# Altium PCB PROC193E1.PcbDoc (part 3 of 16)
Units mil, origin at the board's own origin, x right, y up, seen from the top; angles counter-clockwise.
Board outline 7700 x 2300 mil, 6 copper layers (Top Layer, GND 1, SIG 1, PWR, GND 2, Bottom Layer), stack 60.98 mil thick; 946 components, 667 nets, 9401 pads, 1730 vias.
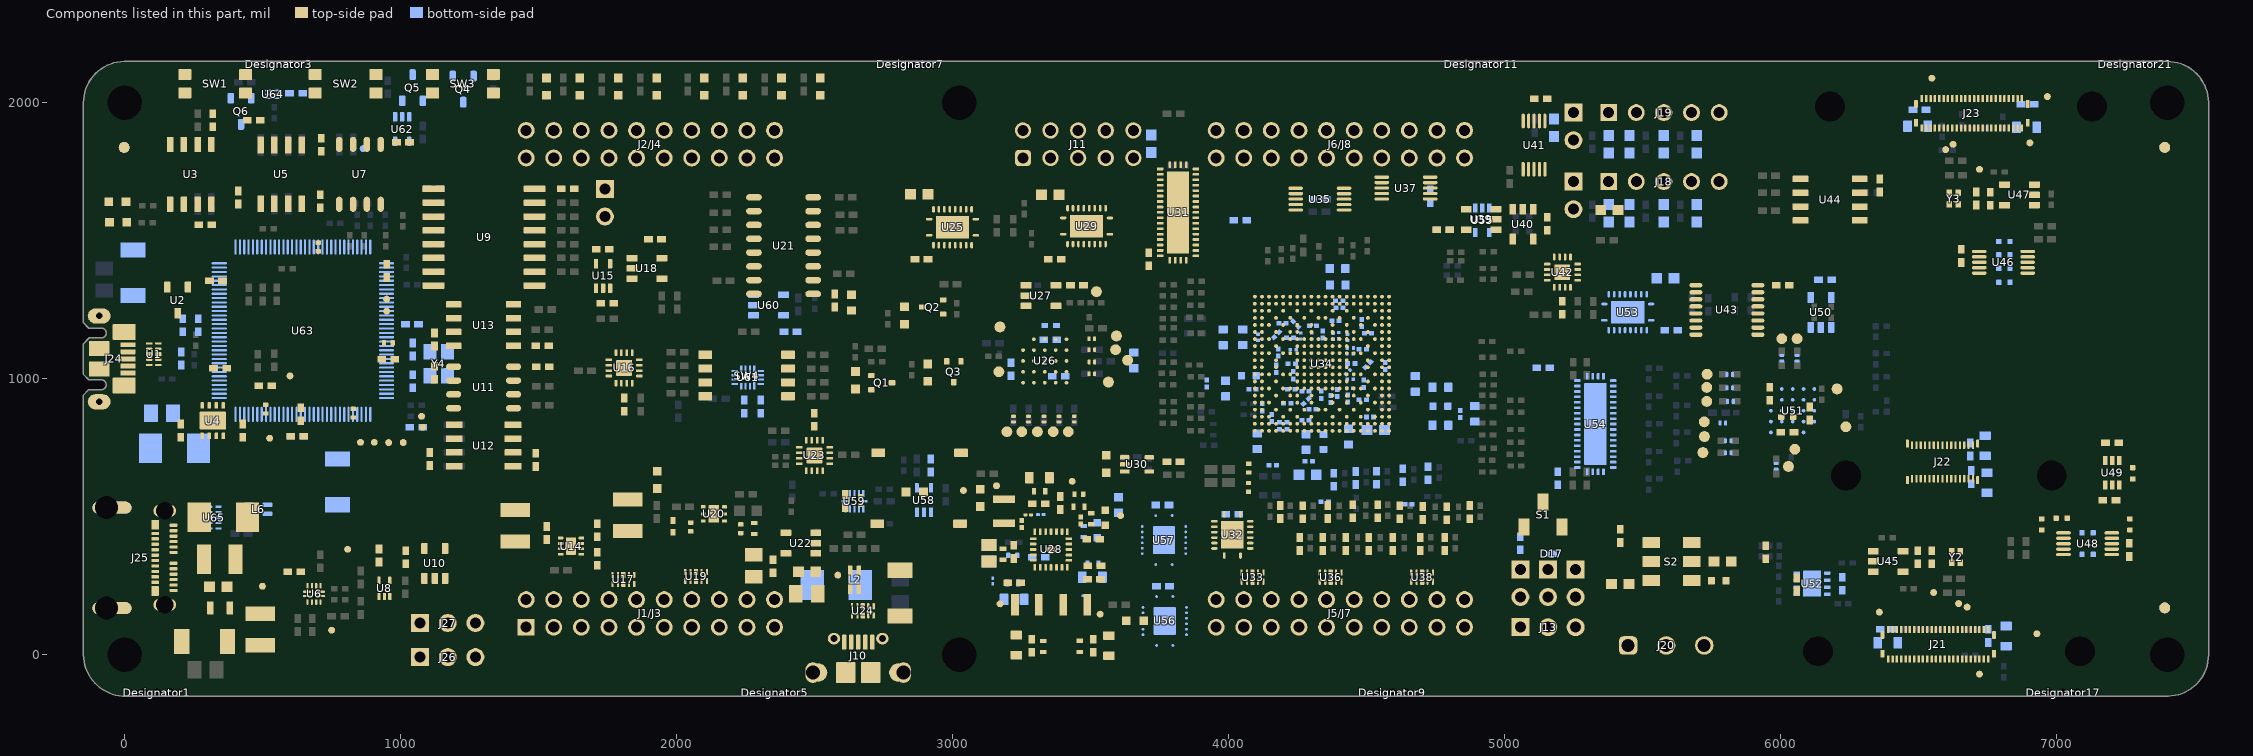
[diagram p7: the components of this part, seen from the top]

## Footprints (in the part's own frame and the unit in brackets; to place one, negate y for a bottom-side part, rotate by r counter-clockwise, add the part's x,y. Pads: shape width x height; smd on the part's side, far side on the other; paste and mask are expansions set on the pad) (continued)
BOOSTERPACK_40PIN_J5J7 [mm] "Receptacle, 2.54mm, 10x2, TH"
  round 1.55 hole 1.02: 41(1.27,11.43) 42(1.27,8.89) 43(1.27,6.35) 44(1.27,3.81) 45(1.27,1.27) 46(1.27,-1.27) 47(1.27,-3.81) 48(1.27,-6.35) 49(1.27,-8.89) 50(1.27,-11.43) 61(-1.27,11.43) 62(-1.27,8.89) 63(-1.27,6.35) 64(-1.27,3.81) 65(-1.27,1.27) 66(-1.27,-1.27) 67(-1.27,-3.81) 68(-1.27,-6.35) 69(-1.27,-8.89) 70(-1.27,-11.43)
  silkscreen extent -2.48,-12.95 2.48,12.95, body extent -2.48,-12.95 2.48,12.95, height 8.51
BoosterPack_40pin_J6J8 [mm] "Receptacle, 2.54mm, 10x2, TH"
  round 1.55 hole 1.02: 51(-1.27,-11.43) 52(-1.27,-8.89) 53(-1.27,-6.35) 54(-1.27,-3.81) 55(-1.27,-1.27) 56(-1.27,1.27) 57(-1.27,3.81) 58(-1.27,6.35) 59(-1.27,8.89) 60(-1.27,11.43) 71(1.27,-11.43) 72(1.27,-8.89) 73(1.27,-6.35) 74(1.27,-3.81) 75(1.27,-1.27) 76(1.27,1.27) 77(1.27,3.81) 78(1.27,6.35) 79(1.27,8.89) 80(1.27,11.43)
  silkscreen extent -7.62,-12.95 2.48,12.95, body extent -2.48,-12.95 2.48,12.95, height 8.51
BRAKE_WAY_HOLES1X3 [mil]
  round 27 hole 32 unplated mask+5.5: ""(-50,49.37) ""(0,49.37) ""(50,49.37)
CE_Mark_5mm [mil] "Minimum text height for CE Mark"
  silkscreen extent -138,-98 138,98
D0008A-MFG [mm]
  rrect17% 1.55x0.6 smd paste+0 mask+0: 1(-2.7,1.905) 2(-2.7,0.635) 3(-2.7,-0.635) 4(-2.7,-1.905) 5(2.7,-1.905) 6(2.7,-0.635) 7(2.7,0.635) 8(2.7,1.905)
  silkscreen extent -4.17,-2.5 1.5,2.5, body extent -3.57,-2.75 3.57,2.75, height 0.25
D0008B_HV [mm] "SOIC, 8-Leads, Body 4.9x3.9mm, Pitch 1.27mm, HV / Isolation option"
  rrect17% 1.4x0.6 smd: 1(-2.75,1.905) 2(-2.75,0.635) 3(-2.75,-0.635) 4(-2.75,-1.905) 5(2.75,-1.905) 6(2.75,-0.635) 7(2.75,0.635) 8(2.75,1.905)
  silkscreen extent -3.3,-2.5 0.9,2.5, body extent -3,-2.45 3,2.45, height 1.63
D0008B_N [mil] "SOIC, 8-Leads, Body 4.9x3.9mm, Pitch 1.27mm, IPC Medium Density"
  oval 55x23.62 smd: 1(-108.5,75) 2(-108.5,25) 3(-108.5,-25) 4(-108.5,-75) 5(108.5,-75) 6(108.5,-25) 7(108.5,25) 8(108.5,75)
  silkscreen extent -130,-98 35,98, body extent -118,-96 118,96, height 64
D0016A_N [mm] "SOIC, 16-Leads, Body 9.9x3.9mm, Pitch 1.27mm, IPC Medium Density"
  oval 1.45x0.6 smd: 1(-2.725,4.445) 2(-2.725,3.175) 3(-2.725,1.905) 4(-2.725,0.635) 5(-2.725,-0.635) 6(-2.725,-1.905) 7(-2.725,-3.175) 8(-2.725,-4.445) 9(2.725,-4.445) 10(2.725,-3.175) 11(2.725,-1.905) 12(2.725,-0.635) 13(2.725,0.635) 14(2.725,1.905) 15(2.725,3.175) 16(2.725,4.445)
  silkscreen extent -3.3,-5 0.9,5, body extent -3,-4.95 3,4.95, height 1.6
DBV0005A_N [mm] "SOT23, 5-Leads, Body 2.9x1.6mm, Pitch 0.95mm, Lead Span 2.8mm, IPC Medium Density"
  rrect17% 1x0.6 smd: 1(-1.375,0.95) 2(-1.375,0) 3(-1.375,-0.95) 4(1.375,-0.95) 5(1.375,0.95)
  silkscreen extent -0.25,-1.55 0.25,1.55, body extent -1.42,-1.46 1.42,1.46, height 1.09
DBZ0003A_N [mm] "SOT23, 3-Leads, Body 2.9x1.3mm, Pitch 0.95mm, Lead Span 2.4mm, IPC Medium Density"
  rrect17% 1x0.6 smd: 1(-1.2,0.95) 2(-1.2,-0.95) 3(1.2,0)
  silkscreen extent 0.2,-1.5 0.7,1.5, body extent -1.26,-1.46 1.26,1.46, height 0.98
DCK0005A_N [mm] "SOT353, 5-Leads, Body 2x1.3mm, Pitch 0.65mm, Lead Span 2.1mm, IPC Medium Density"
  rrect25% 0.85x0.4 smd: 1(-1.125,0.65) 2(-1.125,0) 3(-1.125,-0.65) 4(1.125,-0.65) 5(1.125,0.65)
  silkscreen extent -1.48,-1.02 0.55,1.1, body extent -1.14,-1 1.14,1, height 0.95
DCK0006A_N [mm] "SOT23, 6-Leads, Body 2x1.3mm, Pitch 0.65mm, Lead Span 2.1mm, IPC Medium Density"
  rrect25% 0.85x0.4 smd: 1(-1.125,0.65) 2(-1.125,0) 3(-1.125,-0.65) 4(1.125,-0.65) 5(1.125,0) 6(1.125,0.65)
  silkscreen extent -1.5,-1.09 0.51,1.09, body extent -1.14,-1 1.14,1, height 0.95
DGS0010A_N [mm] "TSSOP, 10-Leads, Body 3x3mm, Pitch 0.5mm, IPC Medium Density"
  oval 1.35x0.3 smd: 1(-2.225,1) 2(-2.225,0.5) 3(-2.225,0) 4(-2.225,-0.5) 5(-2.225,-1) 6(2.225,-1) 7(2.225,-0.5) 8(2.225,0) 9(2.225,0.5) 10(2.225,1)
  silkscreen extent -2.75,-1.55 0.9,1.55, body extent -2.45,-1.5 2.45,1.5, height 0.96
DPY0002A [mm] "X1SON-2"
  rrect57% 0.35x0.6 smd paste-0.5 mask-0.05: 1(-0.325,0) 2(0.325,0)
  rrect33% 0.3x0.5 on Bottom Paste: 1S(-0.35,0) 2S(0.35,0)
  silkscreen extent -0.85,-0.02 -0.8,0.02, body extent -0.5,-0.3 0.5,0.3, height 0.45
DQA0010A#1 [mm] "SON, 10-Leads, Body 1x2.5mm, Pitch 0.5mm, TI Recommended"
  rrect50% 0.565x0.2 smd: 1(-0.417,1) 2(-0.417,0.5) 4(-0.417,-0.5) 5(-0.417,-1) 6(0.417,-1) 7(0.417,-0.5) 9(0.417,0.5) 10(0.417,1)
  rrect28% 0.565x0.36 on Top Paste: 3(-0.417,0) 8(0.417,0)
  rrect25% 0.565x0.4 smd paste-0.2: 3(-0.417,0) 8(0.417,0)
  silkscreen extent -0.67,-1.45 0.55,1.45, body extent -0.55,-1.3 0.55,1.3, height 0.56
DQA0010A#2 [mm] "SON, 10-Leads, Body 1x2.5mm, Pitch 0.5mm, TI Recommended"
  rrect50% 0.565x0.2 smd: 1(-0.417,1) 2(-0.417,0.5) 4(-0.417,-0.5) 5(-0.417,-1) 6(0.417,-1) 7(0.417,-0.5) 9(0.417,0.5) 10(0.417,1)
  rrect28% 0.565x0.36 on Bottom Paste: 3(-0.417,0) 8(0.417,0)
  rrect25% 0.565x0.4 smd paste-0.2: 3(-0.417,0) 8(0.417,0)
  silkscreen extent -0.67,-1.45 0.55,1.45, body extent -0.55,-1.3 0.55,1.3, height 0.56
DRB0008B [mm] "SON, 8-Leads, Body 3x3mm, Pitch 0.65mm, Thermal Pad 2.4x1.65mm, TI Recommended"
  rrect33% 0.6x0.3 smd: 1(-1.4,0.975) 2(-1.4,0.325) 3(-1.4,-0.325) 4(-1.4,-0.975) 5(1.4,-0.975) 6(1.4,-0.325) 7(1.4,0.325) 8(1.4,0.975)
  rrect50% 1.47x1.06 on Top Paste: 9(0,0.63) 9(0,-0.63)
  rrect6% 1.65x2.4 smd paste-1.2: 9(0,0)
  silkscreen extent -1.73,-1.73 1.73,1.73, body extent -1.5,-1.5 1.5,1.5, height 0.96
DRB0008J [mm] "VSON-8"
  rrect33% 0.6x0.31 smd: 1(-1.4,0.975) 2(-1.4,0.325) 3(-1.4,-0.325) 4(-1.4,-0.975) 5(1.4,-0.975) 6(1.4,-0.325) 7(1.4,0.325) 8(1.4,0.975)
  rrect6% 1.65x2.4 smd paste-1.2: 9(0,0)
  silkscreen extent -1.73,-1.73 1.73,1.73, body extent -1.55,-1.55 1.55,1.55, height 1.01
DRL0005A [mm] "SOTFL, 5-Flat Leads, Body 1.2x1.6x0.6mm, Pitch 0.5mm, TI recommended"
  rrect33% 0.67x0.3 smd: 1(-0.74,0.5) 2(-0.74,0) 3(-0.74,-0.5) 4(0.74,-0.5) 5(0.74,0.5)
  silkscreen extent -0.9,-0.95 0.5,0.95, body extent -0.85,-0.85 0.85,0.85, height 0.62
DRV0006A [mm] "SON, 6-Leads, Body 2x2mm, Pitch 0.65mm, Thermal Pad 1.6x1mm, TI Recommended"
  rrect33% 0.45x0.3 smd: 1(-0.975,0.65) 2(-0.975,0) 3(-0.975,-0.65) 4(0.975,-0.65) 5(0.975,0) 6(0.975,0.65)
  rrect14% 1x0.7 on Top Paste: 7(0,0.45) 7(0,-0.45)
  rrect10% 1x1.6 smd paste-0.5: 7(0,0)
  silkscreen extent -1.05,-1.2 1.05,1.2, body extent -1.05,-1.05 1.05,1.05, height 0.81
DSF0006A [mm] "TI recommended land pattern"
  rrect59% 0.6x0.17 smd mask+0.045: 1(-0.4,0.35) 2(-0.4,0) 3(-0.4,-0.35) 4(0.4,-0.35) 5(0.4,0) 6(0.4,0.35)
  silkscreen extent -0.6,-0.63 0.6,0.63, body extent -0.5,-0.5 0.5,0.5, height 0.48
DSG0008B [mm] "SON, 8-Leads, Body 2x2mm, Pitch 0.5mm, Thermal Pad 1.6x0.9mm, TI Recommended"
  rrect14% 0.9x0.7 on Top Paste: 0(0,-0.45) 0(0,0.45)
  rrect40% 0.5x0.25 smd: 1(-0.95,0.75) 2(-0.95,0.25) 3(-0.95,-0.25) 4(-0.95,-0.75) 5(0.95,-0.75) 6(0.95,-0.25) 7(0.95,0.25) 8(0.95,0.75)
  rrect11% 0.9x1.6 smd paste-0.45: 9(0,0)
  silkscreen extent -1.07,-1.15 1.07,1.15, body extent -1,-1 1,1, height 0.77
DW0016A-MFG [mm]
  rrect17% 2x0.6 smd paste+0 mask+0: 1(-4.65,4.445) 2(-4.65,3.175) 3(-4.65,1.905) 4(-4.65,0.635) 5(-4.65,-0.635) 6(-4.65,-1.905) 7(-4.65,-3.175) 8(-4.65,-4.445) 9(4.65,-4.445) 10(4.65,-3.175) 11(4.65,-1.905) 12(4.65,-0.635) 13(4.65,0.635) 14(4.65,1.905) 15(4.65,3.175) 16(4.65,4.445)
  silkscreen extent -6.32,-5.25 3.15,5.25, body extent -5.75,-5.35 5.75,5.35, height 0.25
FCC_disclaimer [mil]
Fiducial10-20 [mm]
  round 1 smd mask+0.5: 1(0,0)
  Top Layer keep-out circle w1.178: c0,0 r0.5
FP-2012670005_CONN_USB_9MM39_8MM21-MFG [mm]
  rrect100% 1.1x2.1 hole 1.6 slot 0.6 at 0 deg paste-2539.97 mask+0: 1(-4.32,3.205) 2(4.32,3.205)
  rrect100% 1.1x3.6 smd paste-1000 mask+0: 3(-4.62,-1.655) 4(4.62,-1.655)
  rrect100% 1.1x3.6 smd far side paste-1000 mask+0: 3(-4.62,-1.655) 4(4.62,-1.655)
  rrect100% 0.6x2.1 hole 2.1 slot 0.6 at 0 deg paste-2539.97 mask+0: 3(-4.62,-2.155) 4(4.62,-2.155)
  rrect33% 0.3x0.7 smd paste+0 mask+0: A1(-3,4.015) A2(-2.5,4.015) A3(-2,4.015) A4(-1.5,4.015) A5(-1,4.015) A6(-0.5,4.015) A7(0.5,4.015) A8(1,4.015) A9(1.5,4.015) A10(2,4.015) A11(2.5,4.015) A12(3,4.015) B2(2.25,2.315) B3(1.75,2.315) B4(1.25,2.315) B5(0.75,2.315) B6(0.25,2.315) B7(-0.25,2.315) B8(-0.75,2.315) B9(-1.25,2.315) B10(-1.75,2.315) B11(-2.25,2.315)
  rrect14% 0.9x0.7 smd paste+0 mask+0: B1(3.05,2.315) B12(-3.05,2.315)
  silkscreen extent -4.77,0.52 4.77,5.04, body extent -5.27,-4.33 5.27,4.46, height 0.25
FP-416131160801_DIP_SW_1-MFG [mm]
  rrect13% 1.27x0.76 smd paste+0 mask+0: 1(-3.81,0) 2(3.81,0)
  silkscreen extent -5.12,-1.37 2.93,1.37, body extent -4.54,-1.47 4.54,1.47, height 0.25
FP-416131160804_SMT_SW-MFG [mm]
  rrect13% 0.76x1.27 smd paste+0 mask+0: 1(-1.905,-3.81) 2(-0.635,-3.81) 3(0.635,-3.81) 4(1.905,-3.81) 5(1.905,3.81) 6(0.635,3.81) 7(-0.635,3.81) 8(-1.905,3.81)
  silkscreen extent -3.27,-4.12 3.27,2.93, body extent -3.37,-4.54 3.37,4.54, height 0.25
FP-434351045816_SMT_SW_4MM7_4MM5-MFG [mm]
  rrect10% 1.2x1 smd paste+0 mask+0: 1(2.8,0.85) 2(2.8,-0.85) 3(-2.8,0.85) 4(-2.8,-0.85)
  silkscreen extent -2.4,0.73 4.07,1.85, body extent -3.5,-2.95 3.5,1.95, height 0.25
FP-629105150921_CONN_PTH_USB_8MM0_5MM6-MFG [mm]
  rrect25% 0.4x1.35 smd paste+0 mask+0: 1(-1.3,2.335) 2(-0.65,2.335) 3(0,2.335) 4(0.65,2.335) 5(1.3,2.335)
  rrect100% 1.15x1.05 hole 0.65 slot 0.75 at 0 deg paste-2539.97 mask+0: 6(-2.225,2.65) 7(2.225,2.65)
  rrect100% 1.35x1.9 hole 1.3 slot 0.75 at 0 deg paste-2539.97 mask+0: 8(-4.175,-0.47) 11(4.173,-0.47)
  round 1.71 smd paste+0 mask+0: 8(-3.699,-0.47) 11(3.699,-0.47)
  rrect6% 1.8x1.9 smd paste+0 mask+0: 9(-1.15,-0.47) 10(1.15,-0.47)
  Top Layer region: -2.6,-1.42 -4.35,-1.42 -4.541,-1.382 -4.704,-1.274 -4.812,-1.111 -4.85,-0.92 -4.85,-0.92 -4.85,-0.02 -4.812,0.171 -4.704,0.334 -4.541,0.442 -4.35,0.48 -4.35,0.48 -2.6,0.48
  Top Layer region: 2.6,0.48 4.35,0.48 4.541,0.442 4.704,0.334 4.812,0.171 4.85,-0.02 4.85,-0.02 4.85,-0.92 4.812,-1.111 4.704,-1.274 4.541,-1.382 4.35,-1.42 4.35,-1.42 2.6,-1.42
  silkscreen extent -3.8,0.86 3.8,3.71, body extent -4.95,-2.7 4.95,3.27, height 0.25
FP-ASCO-25.000MHZ-EK-T3_SMT4_1MM6_1MM2-MFG [mm]
  rrect20% 0.6x0.5 smd paste+0 mask+0: 1(-0.55,-0.4) 2(0.55,-0.4) 3(0.55,0.4) 4(-0.55,0.4)
  silkscreen extent -1.22,-1.35 1.22,0.65, body extent -0.8,-0.6 0.8,0.6, height 0.7
FP-BLM18EG121SN1D_0603-MFG [mm]
  rrect15% 0.65x0.7 smd paste+0 mask+0: 1(-0.675,0) 2(0.675,0)
  silkscreen extent -0.87,-0.8 0.87,0.8, body extent -1.1,-0.58 1.1,0.58, height 0.25
FP-BLM21PG300SN1D_0805-MFG [mm]
  rrect17% 0.6x1.2 smd paste-1000 mask-1000: 1(-0.9,0) 2(0.9,0)
  silkscreen extent -0.23,-0.72 0.23,0.72, body extent -1.3,-0.82 1.3,0.82, height 0.25
FP-CGA3E3X7S1A225K080AB_0603-MFG [mm]
  rrect14% 0.7x0.7 smd paste+0 mask+0: 1(-0.7,0) 2(0.7,0)
  silkscreen extent -0.95,-0.73 0.95,0.72, body extent -1.15,-0.65 1.15,0.65, height 0.25
FP-CGA4J3X7S1A106K125AE_0805-MFG [mm]
  rrect13% 0.8x1.05 smd paste+0 mask+0: 1(-0.925,0) 2(0.925,0)
  silkscreen extent -0.15,-0.75 0.15,0.75, body extent -1.2,-0.62 1.2,0.63, height 1.5
FP-CL10A335KP8NNNC_0603-MFG [mm]
  rrect13% 0.76x0.85 smd paste+0 mask+0: 1(-0.72,0) 2(0.72,0)
  silkscreen extent -0.85,-0.8 0.85,0.8, body extent -1.2,-0.55 1.2,0.55, height 0.25
"FP-CRCW020122R0FNED_0201 (0603 metric)-MFG" [mm]
  rrect36% 0.28x0.43 smd paste+0 mask+0: 1(-0.255,0) 2(0.255,0)
  body extent -0.3,-0.15 0.3,0.15, height 0.28
FP-DF40GB(1.5)-30DS-0.4V(58)_HDR30-MFG [mm]
  rrect50% 0.2x0.7 smd paste-1000 mask+0: 1(-2.8,-1.54) 2(-2.8,1.54) 3(-2.4,-1.54) 4(-2.4,1.54) 5(-2,-1.54) 6(-2,1.54) 7(-1.6,-1.54) 8(-1.6,1.54) 9(-1.2,-1.54) 10(-1.2,1.54) 11(-0.8,-1.54) 12(-0.8,1.54) 13(-0.4,-1.54) 14(-0.4,1.54) 15(0,-1.54) 16(0,1.54) 17(0.4,-1.54) 18(0.4,1.54) 19(0.8,-1.54) 20(0.8,1.54) 21(1.2,-1.54) 22(1.2,1.54) 23(1.6,-1.54) 24(1.6,1.54) 25(2,-1.54) 26(2,1.54) 27(2.4,-1.54) 28(2.4,1.54) 29(2.8,-1.54) 30(2.8,1.54)
  rrect36% 0.28x0.72 smd paste-1000 mask+0: 31(-3.24,1.68) 32(3.24,1.68) 33(-3.24,-1.68) 34(3.24,-1.68)
  silkscreen extent -4.47,-2.56 4.47,1.84, body extent -4.57,-2.14 4.57,2.14, height 0.25
FP-DF40GB-48DP-0.4V(58)_HDR48-MFG [mm]
  rrect43% 0.23x0.66 smd paste-1000 mask+0: 1(-4.6,-1.355) 2(-4.6,1.355) 3(-4.2,-1.355) 4(-4.2,1.355) 5(-3.8,-1.355) 6(-3.8,1.355) 7(-3.4,-1.355) 8(-3.4,1.355) 9(-3,-1.355) 10(-3,1.355) 11(-2.6,-1.355) 12(-2.6,1.355) 13(-2.2,-1.355) 14(-2.2,1.355) 15(-1.8,-1.355) 16(-1.8,1.355) 17(-1.4,-1.355) 18(-1.4,1.355) 19(-1,-1.355) 20(-1,1.355) 21(-0.6,-1.355) 22(-0.6,1.355) 23(-0.2,-1.355) 24(-0.2,1.355) 25(0.2,-1.355) 26(0.2,1.355) 27(0.6,-1.355) 28(0.6,1.355) 29(1,-1.355) 30(1,1.355) 31(1.4,-1.355) 32(1.4,1.355) 33(1.8,-1.355) 34(1.8,1.355) 35(2.2,-1.355) 36(2.2,1.355) 37(2.6,-1.355) 38(2.6,1.355) 39(3,-1.355) 40(3,1.355) 41(3.4,-1.355) 42(3.4,1.355) 43(3.8,-1.355) 44(3.8,1.355) 45(4.2,-1.355) 46(4.2,1.355) 47(4.6,-1.355) 48(4.6,1.355)
  rrect29% 0.35x0.7 smd paste-1000 mask+0: 49(-5.135,0.86) 50(5.135,0.86) 51(-5.135,-0.86) 52(5.135,-0.86)
  Top Layer keep-out region: -6.17,1.685 -4.86,1.685 -4.86,0.94 -5.46,0.94 -5.46,-0.94 -4.86,-0.94 -4.86,-1.685 -6.17,-1.685
  Top Layer keep-out region: 6.17,1.685 4.86,1.685 4.86,0.94 5.46,0.94 5.46,-0.94 4.86,-0.94 4.86,-1.685 6.17,-1.685
  silkscreen extent -5.53,-2.37 5.53,0.14, body extent -5.63,-1.79 5.63,1.79, height 0.25
FP-ERJ-2GEJ152X_0402-MFG [mm]
  rrect21% 0.475x0.5 smd paste+0 mask+0: 1(-0.512,0) 2(0.513,0)
  silkscreen extent -0.53,-0.63 0.53,0.63, body extent -0.5,-0.25 0.5,0.25, height 0.4
FP-GJM1555C1H120JB01D_0402-MFG [mm]
  rrect25% 0.4x0.5 smd paste+0 mask+0: 1(-0.4,0) 2(0.4,0)
  silkscreen extent -0.53,-0.63 0.53,0.63, body extent -0.7,-0.38 0.7,0.38, height 0.25
FP-GRM033C80J105ME05D_0201-MFG [mm]
  rrect33% 0.3x0.35 smd paste+0 mask+0: 1(-0.282,0) 2(0.283,0)
  body extent -0.3,-0.15 0.3,0.15, height 0.39
FP-GRM155C71A105KE11D_0402-MFG [mm]
  rrect25% 0.4x0.5 smd paste+0 mask+0: 1(-0.4,0) 2(0.4,0)
  silkscreen extent -0.55,-0.65 0.55,0.65, body extent -0.7,-0.4 0.7,0.4, height 0.25
FP-GRM155R71H104KE14D_0402-MFG [mm]
  rrect25% 0.4x0.5 smd paste+0 mask+0: 1(-0.4,0) 2(0.4,0)
  silkscreen extent -0.5,-0.65 0.5,0.65, body extent -0.7,-0.38 0.7,0.38, height 0.25
FP-IS25WX064-JHLE_TFBGA24-IPC_C [mm]
  round 0.34 smd paste+0 mask+0: A2(-1,2) A3(0,2) A4(1,2) A5(2,2) B1(-2,1) B2(-1,1) B3(0,1) B4(1,1) B5(2,1) C1(-2,0) C2(-1,0) C3(0,0) C4(1,0) C5(2,0) D1(-2,-1) D2(-1,-1) D3(0,-1) D4(1,-1) D5(2,-1) E1(-2,-2) E2(-1,-2) E3(0,-2) E4(1,-2) E5(2,-2)
  silkscreen extent -3.53,-4 3,4, body extent -3.1,-4.1 3.1,4.1, height 0.25
FP-KGM05CR51A106MH_0402-MFG [mm]
  rrect20% 0.6x0.5 smd paste+0 mask+0: 1(-0.55,0) 2(0.55,0)
  silkscreen extent -0.6,-0.63 0.6,0.63, body extent -0.5,-0.25 0.5,0.25, height 0.7
FP-MX25UW6445GXDQ00_BGA24-IPC_C [mm]
  round 0.34 smd paste+0 mask+0: A2(-1,2) A3(0,2) A4(1,2) A5(2,2) B1(-2,1) B2(-1,1) B3(0,1) B4(1,1) B5(2,1) C1(-2,0) C2(-1,0) C3(0,0) C4(1,0) C5(2,0) D1(-2,-1) D2(-1,-1) D3(0,-1) D4(1,-1) D5(2,-1) E1(-2,-2) E2(-1,-2) E3(0,-2) E4(1,-2) E5(2,-2)
  silkscreen extent -3.7,-4 3,4, body extent -3,-4 3,4, height 1.2
"FP-RC0201JR-070RL_0201 (0603 Metric)-IPC_C" [mil]
  rrect38% 13.94x10.34 smd paste+0 mask+0: 1(-10.01,0) 2(10.01,0)
  body extent -21,-10 21,10, height 10
IND_DLW21S [mm] "muRata"
  rrect25% 0.4x0.9 smd: 1(-0.4,0.85) 2(-0.4,-0.85) 3(0.4,-0.85) 4(0.4,0.85)
  silkscreen extent -1.23,0.66 -0.98,0.92, body extent -0.6,-1 0.6,1, height 1.21
Label_650x200 [mil] "Thermal Transfer Label"
  round 1 on Mech13: 0(0,0)
  silkscreen extent -325,-100 325,100, body extent -325,-100 325,100, height 1
MHNP_M2-5_PANHEAD_PHILLIPS [mil]
  round 103 hole 108 unplated mask+5.5: ""(0,0)
  Keep-Out Layer circle w1: c0,0 r108
MHNP_M3_PANHEAD_PHILLIPS#1 [mil]
  round 121 hole 126 unplated mask+5.5: ""(-4.17,0)
  Keep-Out Layer circle w1: c0,0 r126
MHNP_M3_PANHEAD_PHILLIPS#2 [mil]
  round 121 hole 126 unplated mask+5.5: ""(0,0)
  Keep-Out Layer circle w1: c0,0 r126
MISTRAL_LOGO_25 [mil]
  silkscreen extent 0,0 297,162
Molex_1051640001 [mm] "Receptacle, USB 2.0, Micro B, 5 Pos, 0.65mm Pitch, R/A, SMT"
  rrect22% 0.45x1.38 smd: 1(1.3,4.11) 2(0.65,4.11) 3(0,4.11) 4(-0.65,4.11) 5(-1.3,4.11)
  rrect7% 1.475x2.1 smd: 6(-2.462,3.75) 11(2.462,3.75)
  rrect100% 1.4x2.1 hole 0.6 slot 1.3 at 90 deg: 7(-3.95,1.45) 10(3.95,1.45)
  rrect7% 1.375x1.9 smd: 8(-0.937,1.45) 9(0.937,1.45)
  silkscreen extent 1.2,5.1 1.4,5.4, body extent -4.1,-0.7 4.1,4.47, height 2.45
NDK_NX3225GA [mm] "NDK"
  rect 1.2x1.4 smd: 1(-0.8,1.1) 2(-0.8,-1.1) 3(0.8,-1.1) 4(0.8,1.1)
  silkscreen extent -1.9,-0.1 1.4,2, body extent -1.3,-1.65 1.3,1.65, height 0.9
On-Shore_OSTTE030161 [mm] "Terminal Block, 3.5mm, 3x1, TH"
  rrect50% 1.7x1.7 hole 1.2: 1(-3.5,0)
  round 1.7 hole 1.2: 2(0,0) 3(3.5,0)
  silkscreen extent -5.25,-3.6 5.25,4.05, body extent -5.75,-3.6 5.75,3.4, height 8.4
PBC03SAAN [mm] "Sullins 100mil, 1x3, 230 mil above insulator"
  rect 1.65x1.65 hole 1.016: 1(-2.54,0)
  round 1.65 hole 1.016: 2(0,0) 3(2.54,0)
  silkscreen extent -3.81,-1.27 3.81,1.27, body extent -3.81,-1.27 3.81,1.27, height 8.38
PDT0128A [mm] "Thin QFP, 128-Leads, Body 14x14mm, Pitch 0.4mm"
  oval 1.4x0.2 smd: 1(-7.7,6.2) 2(-7.7,5.8) 3(-7.7,5.4) 4(-7.7,5) 5(-7.7,4.6) 6(-7.7,4.2) 7(-7.7,3.8) 8(-7.7,3.4) 9(-7.7,3) 10(-7.7,2.6) 11(-7.7,2.2) 12(-7.7,1.8) 13(-7.7,1.4) 14(-7.7,1) 15(-7.7,0.6) 16(-7.7,0.2) 17(-7.7,-0.2) 18(-7.7,-0.6) 19(-7.7,-1) 20(-7.7,-1.4) 21(-7.7,-1.8) 22(-7.7,-2.2) 23(-7.7,-2.6) 24(-7.7,-3) 25(-7.7,-3.4) 26(-7.7,-3.8) 27(-7.7,-4.2) 28(-7.7,-4.6) 29(-7.7,-5) 30(-7.7,-5.4) 31(-7.7,-5.8) 32(-7.7,-6.2) 65(7.7,-6.2) 66(7.7,-5.8) 67(7.7,-5.4) 68(7.7,-5) 69(7.7,-4.6) 70(7.7,-4.2) 71(7.7,-3.8) 72(7.7,-3.4) 73(7.7,-3) 74(7.7,-2.6) 75(7.7,-2.2) 76(7.7,-1.8) 77(7.7,-1.4) 78(7.7,-1) 79(7.7,-0.6) 80(7.7,-0.2) 81(7.7,0.2) 82(7.7,0.6) 83(7.7,1) 84(7.7,1.4) 85(7.7,1.8) 86(7.7,2.2) 87(7.7,2.6) 88(7.7,3) 89(7.7,3.4) 90(7.7,3.8) 91(7.7,4.2) 92(7.7,4.6) 93(7.7,5) 94(7.7,5.4) 95(7.7,5.8) 96(7.7,6.2)
  oval 0.2x1.4 smd: 33(-6.2,-7.7) 34(-5.8,-7.7) 35(-5.4,-7.7) 36(-5,-7.7) 37(-4.6,-7.7) 38(-4.2,-7.7) 39(-3.8,-7.7) 40(-3.4,-7.7) 41(-3,-7.7) 42(-2.6,-7.7) 43(-2.2,-7.7) 44(-1.8,-7.7) 45(-1.4,-7.7) 46(-1,-7.7) 47(-0.6,-7.7) 48(-0.2,-7.7) 49(0.2,-7.7) 50(0.6,-7.7) 51(1,-7.7) 52(1.4,-7.7) 53(1.8,-7.7) 54(2.2,-7.7) 55(2.6,-7.7) 56(3,-7.7) 57(3.4,-7.7) 58(3.8,-7.7) 59(4.2,-7.7) 60(4.6,-7.7) 61(5,-7.7) 62(5.4,-7.7) 63(5.8,-7.7) 64(6.2,-7.7) 97(6.2,7.7) 98(5.8,7.7) 99(5.4,7.7) 100(5,7.7) 101(4.6,7.7) 102(4.2,7.7) 103(3.8,7.7) 104(3.4,7.7) 105(3,7.7) 106(2.6,7.7) 107(2.2,7.7) 108(1.8,7.7) 109(1.4,7.7) 110(1,7.7) 111(0.6,7.7) 112(0.2,7.7) 113(-0.2,7.7) 114(-0.6,7.7) 115(-1,7.7) 116(-1.4,7.7) 117(-1.8,7.7) 118(-2.2,7.7) 119(-2.6,7.7) 120(-3,7.7) 121(-3.4,7.7) 122(-3.8,7.7) 123(-4.2,7.7) 124(-4.6,7.7) 125(-5,7.7) 126(-5.4,7.7) 127(-5.8,7.7) 128(-6.2,7.7)
  silkscreen extent -7.7,-6.3 6.3,6.99, body extent -8,-8 8,8, height 1.07
PW0016A_L [mm] "TSOP, 16-Leads, Body 5x4.4mm, Pitch 0.65mm, IPC High Density"
  oval 1.2x0.4 smd: 1(-2.85,2.275) 2(-2.85,1.625) 3(-2.85,0.975) 4(-2.85,0.325) 5(-2.85,-0.325) 6(-2.85,-0.975) 7(-2.85,-1.625) 8(-2.85,-2.275) 9(2.85,-2.275) 10(2.85,-1.625) 11(2.85,-0.975) 12(2.85,-0.325) 13(2.85,0.325) 14(2.85,0.975) 15(2.85,1.625) 16(2.85,2.275)
  silkscreen extent -2,-2.55 1.85,2.55, body extent -3.21,-2.5 3.21,2.5, height 1
RAY0024B-MFG [mm]
  rrect40% 0.625x0.25 smd paste+0 mask+0: 1(-1.637,1.5) 7(-1.637,-1.5) 13(1.637,-1.5) 19(1.637,1.5)
  rrect40% 0.6x0.25 smd paste+0 mask+0: 2(-1.65,1) 3(-1.65,0.5) 5(-1.65,-0.5) 6(-1.65,-1) 14(1.65,-1) 15(1.65,-0.5) 17(1.65,0.5) 18(1.65,1)
  rrect40% 0.6x0.25 smd paste+0 mask-1000: 4(-1.65,0) 16(1.65,0)
  rrect40% 0.25x0.6 smd paste+0 mask+0: 8(-1,-1.65) 9(-0.5,-1.65) 10(0,-1.65) 11(0.5,-1.65) 12(1,-1.65) 20(1,1.65) 21(0.5,1.65) 22(0,1.65) 23(-0.5,1.65) 24(-1,1.65)
  round 0.777 smd paste-1000 mask+0: ""(0.037,-0.003)
  Top Layer region: -1.95,0.075 -1.943,0.1 -1.925,0.118 -1.9,0.125 -1.9,0.125 -1.4,0.125 -1.378,0.12 -1.361,0.106 -1.361,0.106 -1.344,0.092 -1.322,0.088 -1.322,0.088 -0.426,0.088 -0.406,0.091 -0.39,0.102 -0.379,0.118 -0.375,0.138 -0.376,0.138 -0.376,0.601 -0.369,0.626 -0.35,0.644 -0.325,0.651 -0.326,0.651 0.456,0.651 0.48,0.644 0.499,0.626 0.505,0.601 0.505,0.601 0.505,0.1 0.509,0.081 0.52,0.065 0.536,0.054 0.556,0.05 0.556,0.05 1.303,0.05 1.324,0.055 1.342,0.068 1.352,0.088 1.352,0.088 1.362,0.107 1.379,0.12 1.4,0.125 1.4,0.125 1.9,0.125 1.925,0.118 1.943,0.1 1.95,0.075 1.95,0.075 1.95,-0.075 1.943,-0.1 1.925,-0.118 1.9,-0.125 1.9,-0.125 0.556,-0.125 0.536,-0.129 0.52,-0.14 0.509,-0.156 0.506,-0.175 0.505,-0.175 0.505,-0.601 0.499,-0.626 0.48,-0.644 0.456,-0.651 0.456,-0.651 -0.326,-0.651 -0.35,-0.644 -0.369,-0.626 -0.375,-0.601 -0.375,-0.601 -0.376,-0.138 -0.379,-0.118 -0.39,-0.102 -0.406,-0.091 -0.425,-0.088 -0.426,-0.087 -1.322,-0.088 -1.344,-0.092 -1.361,-0.106 -1.361,-0.106 -1.378,-0.12 -1.4,-0.125 -1.4,-0.125 -1.9,-0.125 -1.925,-0.118 -1.943,-0.1 -1.95,-0.075 -1.95,-0.075
  silkscreen extent -2.62,-2.17 2.17,2.17, body extent -1.75,-1.75 1.75,1.75, height 1
RGT0016A [mm] "QFN, 16-Leads, Body 3x3mm, Pitch 0.5mm, Thermal Pad 1.45x1.45mm, TI Recommended"
  rrect42% 0.6x0.24 smd: 1(-1.4,0.75) 2(-1.4,0.25) 3(-1.4,-0.25) 4(-1.4,-0.75) 9(1.4,-0.75) 10(1.4,-0.25) 11(1.4,0.25) 12(1.4,0.75)
  rrect42% 0.24x0.6 smd: 5(-0.75,-1.4) 6(-0.25,-1.4) 7(0.25,-1.4) 8(0.75,-1.4) 13(0.75,1.4) 14(0.25,1.4) 15(-0.25,1.4) 16(-0.75,1.4)
  rrect7% 1.34x1.34 on Top Paste: 17(0,0)
  rrect7% 1.45x1.45 smd paste-0.725: 17(0,0)
  silkscreen extent -1.72,-1.73 1.72,1.73, body extent -1.5,-1.5 1.5,1.5, height 1
RGY0016A [mm] "QFN, 16-Leads, Body 4x3.5mm, Pitch 0.5mm, Thermal Pad 2.55x2.05mm, TI Recommended"
  oval 0.24x0.6 smd: 1(-0.75,1.9) 8(-0.75,-1.9) 9(0.75,-1.9) 16(0.75,1.9)
  oval 0.6x0.24 smd: 2(-1.65,1.25) 3(-1.65,0.75) 4(-1.65,0.25) 5(-1.65,-0.25) 6(-1.65,-0.75) 7(-1.65,-1.25) 10(1.65,-1.25) 11(1.65,-0.75) 12(1.65,-0.25) 13(1.65,0.25) 14(1.65,0.75) 15(1.65,1.25)
  rect 2.05x2.55 smd paste-1.025: 17(0,0)
  silkscreen extent -1.97,-2.22 1.97,2.23, body extent -1.75,-2 1.75,2, height 1
RGY0016A-MFG [mm]
  round 0.252 smd paste-1000 mask+0: 1(-2.26,-0.75) 2(-1.25,-2) 3(-0.75,-2) 4(-0.25,-2) 5(0.25,-2) 6(0.75,-2) 7(1.25,-2) 8(2.25,-0.75) 9(2.25,0.75) 10(1.25,2) 11(0.75,2) 12(0.25,2) 13(-0.25,2) 14(-0.75,2) 15(-1.25,2) 16(-2.25,0.75)
  rrect5% 2.55x2.05 smd paste-1000 mask+0: 17(0,0)
  Top Layer region: -2.4,0.89 -1.69,0.89 -1.636,0.879 -1.591,0.849 -1.561,0.804 -1.55,0.75 -1.55,0.75 -1.561,0.696 -1.591,0.651 -1.636,0.621 -1.69,0.61 -1.69,0.61 -2.4,0.61
  Top Layer region: 2.4,-0.89 1.69,-0.89 1.636,-0.879 1.591,-0.849 1.561,-0.804 1.55,-0.75 1.55,-0.75 1.561,-0.696 1.591,-0.651 1.636,-0.621 1.69,-0.61 1.69,-0.61 2.4,-0.61
  Top Layer region: 2.4,0.61 1.69,0.61 1.636,0.621 1.591,0.651 1.561,0.696 1.55,0.75 1.55,0.75 1.561,0.804 1.591,0.849 1.636,0.879 1.69,0.89 1.69,0.89 2.4,0.89
  Top Layer region: -2.4,-0.61 -1.69,-0.61 -1.636,-0.621 -1.591,-0.651 -1.561,-0.696 -1.55,-0.75 -1.55,-0.75 -1.561,-0.804 -1.591,-0.849 -1.636,-0.879 -1.69,-0.89 -1.69,-0.89 -2.4,-0.89
  Top Layer region: -1.11,2.15 -1.11,1.44 -1.121,1.386 -1.151,1.341 -1.196,1.311 -1.25,1.3 -1.25,1.3 -1.304,1.311 -1.349,1.341 -1.379,1.386 -1.39,1.44 -1.39,1.44 -1.39,2.15
  Top Layer region: -0.61,2.15 -0.61,1.44 -0.621,1.386 -0.651,1.341 -0.696,1.311 -0.75,1.3 -0.75,1.3 -0.804,1.311 -0.849,1.341 -0.879,1.386 -0.89,1.44 -0.89,1.44 -0.89,2.15
  Top Layer region: -0.11,2.15 -0.11,1.44 -0.121,1.386 -0.151,1.341 -0.196,1.311 -0.25,1.3 -0.25,1.3 -0.304,1.311 -0.349,1.341 -0.379,1.386 -0.39,1.44 -0.39,1.44 -0.39,2.15
  Top Layer region: 0.39,2.15 0.39,1.44 0.379,1.386 0.349,1.341 0.304,1.311 0.25,1.3 0.25,1.3 0.196,1.311 0.151,1.341 0.121,1.386 0.11,1.44 0.11,1.44 0.11,2.15
  Top Layer region: 0.89,2.15 0.89,1.44 0.879,1.386 0.849,1.341 0.804,1.311 0.75,1.3 0.75,1.3 0.696,1.311 0.651,1.341 0.621,1.386 0.61,1.44 0.61,1.44 0.61,2.15
  Top Layer region: 1.39,2.15 1.39,1.44 1.379,1.386 1.349,1.341 1.304,1.311 1.25,1.3 1.25,1.3 1.196,1.311 1.151,1.341 1.121,1.386 1.11,1.44 1.11,1.44 1.11,2.15
  Top Layer region: 1.11,-2.15 1.11,-1.44 1.121,-1.386 1.151,-1.341 1.196,-1.311 1.25,-1.3 1.25,-1.3 1.304,-1.311 1.349,-1.341 1.379,-1.386 1.39,-1.44 1.39,-1.44 1.39,-2.15
  Top Layer region: 0.61,-2.15 0.61,-1.44 0.621,-1.386 0.651,-1.341 0.696,-1.311 0.75,-1.3 0.75,-1.3 0.804,-1.311 0.849,-1.341 0.879,-1.386 0.89,-1.44 0.89,-1.44 0.89,-2.15
  Top Layer region: 0.11,-2.15 0.11,-1.44 0.121,-1.386 0.151,-1.341 0.196,-1.311 0.25,-1.3 0.25,-1.3 0.304,-1.311 0.349,-1.341 0.379,-1.386 0.39,-1.44 0.39,-1.44 0.39,-2.15
  Top Layer region: -0.39,-2.15 -0.39,-1.44 -0.379,-1.386 -0.349,-1.341 -0.304,-1.311 -0.25,-1.3 -0.25,-1.3 -0.196,-1.311 -0.151,-1.341 -0.121,-1.386 -0.11,-1.44 -0.11,-1.44 -0.11,-2.15
  Top Layer region: -0.89,-2.15 -0.89,-1.44 -0.879,-1.386 -0.849,-1.341 -0.804,-1.311 -0.75,-1.3 -0.75,-1.3 -0.696,-1.311 -0.651,-1.341 -0.621,-1.386 -0.61,-1.44 -0.61,-1.44 -0.61,-2.15
  Top Layer region: -1.39,-2.15 -1.39,-1.44 -1.379,-1.386 -1.349,-1.341 -1.304,-1.311 -1.25,-1.3 -1.25,-1.3 -1.196,-1.311 -1.151,-1.341 -1.121,-1.386 -1.11,-1.44 -1.11,-1.44 -1.11,-2.15
  silkscreen extent -2.72,-1.83 2.07,1.83, body extent -2,-1.75 2,1.75, height 1
RGY0020A [mm] "QFN, 20-Leads, Body 4.5x3.5mm, Pitch 0.5mm, Thermal Pad 3.05x2.05mm, TI Recommended"
  oval 0.24x0.6 smd: 1(-0.75,2.15) 10(-0.75,-2.15) 11(0.75,-2.15) 20(0.75,2.15)
  oval 0.6x0.24 smd: 2(-1.65,1.75) 3(-1.65,1.25) 4(-1.65,0.75) 5(-1.65,0.25) 6(-1.65,-0.25) 7(-1.65,-0.75) 8(-1.65,-1.25) 9(-1.65,-1.75) 12(1.65,-1.75) 13(1.65,-1.25) 14(1.65,-0.75) 15(1.65,-0.25) 16(1.65,0.25) 17(1.65,0.75) 18(1.65,1.25) 19(1.65,1.75)
  rect 2.05x3.05 smd paste-1.025: 21(0,0)
  silkscreen extent -1.97,-2.47 1.97,2.48, body extent -1.75,-2.25 1.75,2.25, height 1
RSV0016A [mm] "QFN, 16-Leads, Body 1.8x2.6mm, Pitch 0.4mm, TI Recommended"
  rect 0.7x0.2 smd: 1(-0.75,0.6)
  rect 0.6x0.2 smd: 2(-0.8,0.2) 3(-0.8,-0.2) 4(-0.8,-0.6) 9(0.8,-0.6) 10(0.8,-0.2) 11(0.8,0.2) 12(0.8,0.6)
  rect 0.2x0.6 smd: 5(-0.6,-1.2) 6(-0.2,-1.2) 7(0.2,-1.2) 8(0.6,-1.2) 13(0.6,1.2) 14(0.2,1.2) 15(-0.2,1.2) 16(-0.6,1.2)
  silkscreen extent -1.08,-1.33 1.08,1.33, body extent -0.92,-1.32 0.92,1.33, height 0.56
RUA0042A-MFG [mm]
  rrect40% 0.6x0.25 smd paste+0 mask+0: 1(-1.65,4) 2(-1.65,3.5) 3(-1.65,3) 4(-1.65,2.5) 5(-1.65,2) 6(-1.65,1.5) 7(-1.65,1) 8(-1.65,0.5) 9(-1.65,0) 10(-1.65,-0.5) 11(-1.65,-1) 12(-1.65,-1.5) 13(-1.65,-2) 14(-1.65,-2.5) 15(-1.65,-3) 16(-1.65,-3.5) 17(-1.65,-4) 22(1.65,-4) 23(1.65,-3.5) 24(1.65,-3) 25(1.65,-2.5) 26(1.65,-2) 27(1.65,-1.5) 28(1.65,-1) 29(1.65,-0.5) 30(1.65,0) 31(1.65,0.5) 32(1.65,1) 33(1.65,1.5) 34(1.65,2) 35(1.65,2.5) 36(1.65,3) 37(1.65,3.5) 38(1.65,4)
  rrect40% 0.25x0.6 smd paste+0 mask+0: 18(-0.75,-4.4) 19(-0.25,-4.4) 20(0.25,-4.4) 21(0.75,-4.4) 39(0.75,4.4) 40(0.25,4.4) 41(-0.25,4.4) 42(-0.75,4.4)
  rrect5% 2.05x7.55 smd paste-1000 mask+0: 43(0,0)
  silkscreen extent -2.65,-4.55 1.8,4.55, body extent -1.75,-4.5 1.75,4.5, height 0.8
RUT0012A [mm] "QFN, 12-Leads, Body 1.7x2mm, Pitch 0.4mm, TI Recommended"
  rrect50% 0.7x0.2 smd: 1(-0.7,0.8) 2(-0.7,0.4) 3(-0.7,0) 4(-0.7,-0.4) 5(-0.7,-0.8) 7(0.7,-0.8) 8(0.7,-0.4) 9(0.7,0) 10(0.7,0.4) 11(0.7,0.8)
  rrect50% 0.2x0.7 smd: 6(0,-0.85) 12(0,0.85)
  silkscreen extent -0.9,-1.2 0.9,1.2, body extent -0.85,-1 0.85,1, height 0.55
RWB0012A [mm] "QFN, 12-Leads, Body 1.6x1.6mm, Pitch 0.4mm"
  rrect57% 0.7x0.2 smd paste-0.1: 1(-0.65,0.2) 2(-0.65,-0.2) 7(0.65,-0.2) 8(0.65,0.2)
  rrect57% 0.2x0.5 smd: 3(-0.6,-0.75) 4(-0.2,-0.75) 5(0.2,-0.75) 6(0.6,-0.75) 9(0.6,0.75) 10(0.2,0.75) 11(-0.2,0.75) 12(-0.6,0.75)
  silkscreen extent -0.92,-0.91 0.92,0.91, body extent -0.8,-0.8 0.8,0.8, height 0.4
Sitara_AM261_ZFG0304A [mm] "BGA, 304-Leads, Body 13.25x13.25mmx1.50mm, Pitch 0.65mm"
  round 0.35 smd mask+0.05: A1(-6.175,6.175) A2(-5.525,6.175) A3(-4.875,6.175) A4(-4.225,6.175) A5(-3.575,6.175) A6(-2.925,6.175) A7(-2.275,6.175) A8(-1.625,6.175) A9(-0.975,6.175) A10(-0.325,6.175) A11(0.325,6.175) A12(0.975,6.175) A13(1.625,6.175) A14(2.275,6.175) A15(2.925,6.175) A16(3.575,6.175) A17(4.225,6.175) A18(4.875,6.175) A19(5.525,6.175) A20(6.175,6.175) B1(-6.175,5.525) B2(-5.525,5.525) B3(-4.875,5.525) B4(-4.225,5.525) B5(-3.575,5.525) B6(-2.925,5.525) B7(-2.275,5.525) B8(-1.625,5.525) B9(-0.975,5.525) B10(-0.325,5.525) B11(0.325,5.525) B12(0.975,5.525) B13(1.625,5.525) B14(2.275,5.525) B15(2.925,5.525) B16(3.575,5.525) B17(4.225,5.525) B18(4.875,5.525) B19(5.525,5.525) B20(6.175,5.525) C1(-6.175,4.875) C2(-5.525,4.875) C3(-4.875,4.875) C5(-3.575,4.875) C7(-2.275,4.875) C9(-0.975,4.875) C12(0.975,4.875) C14(2.275,4.875) C16(3.575,4.875) C18(4.875,4.875) C19(5.525,4.875) C20(6.175,4.875) D1(-6.175,4.225) D2(-5.525,4.225) D4(-4.225,4.225) D6(-2.925,4.225) D8(-1.625,4.225) D10(-0.325,4.225) D11(0.325,4.225) D13(1.625,4.225) D15(2.925,4.225) D17(4.225,4.225) D19(5.525,4.225) D20(6.175,4.225) E1(-6.175,3.575) E2(-5.525,3.575) E3(-4.875,3.575) E5(-3.575,3.575) E7(-2.275,3.575) E9(-0.975,3.575) E12(0.975,3.575) E14(2.275,3.575) E16(3.575,3.575) E18(4.875,3.575) E19(5.525,3.575) E20(6.175,3.575) F1(-6.175,2.925) F2(-5.525,2.925) F4(-4.225,2.925) F6(-2.925,2.925) F7(-2.275,2.925) F9(-0.975,2.925) F12(0.975,2.925) F14(2.275,2.925) F15(2.925,2.925) F17(4.225,2.925) F19(5.525,2.925) F20(6.175,2.925) G1(-6.175,2.275) G2(-5.525,2.275) G3(-4.875,2.275) G5(-3.575,2.275) G6(-2.925,2.275) G7(-2.275,2.275) G8(-1.625,2.275) G9(-0.975,2.275) G10(-0.325,2.275) G11(0.325,2.275) G12(0.975,2.275) G13(1.625,2.275) G14(2.275,2.275) G15(2.925,2.275) G16(3.575,2.275) G18(4.875,2.275) G19(5.525,2.275) G20(6.175,2.275) H1(-6.175,1.625) H2(-5.525,1.625) H4(-4.225,1.625) H7(-2.275,1.625) H8(-1.625,1.625) H9(-0.975,1.625) H10(-0.325,1.625) H11(0.325,1.625) H12(0.975,1.625) H13(1.625,1.625) H14(2.275,1.625) H17(4.225,1.625) H19(5.525,1.625) H20(6.175,1.625) J1(-6.175,0.975) J2(-5.525,0.975) J3(-4.875,0.975) J5(-3.575,0.975) J6(-2.925,0.975) J7(-2.275,0.975) J8(-1.625,0.975) J9(-0.975,0.975) J10(-0.325,0.975) J11(0.325,0.975) J12(0.975,0.975) J13(1.625,0.975) J14(2.275,0.975) J15(2.925,0.975) J16(3.575,0.975) J18(4.875,0.975) J19(5.525,0.975) J20(6.175,0.975) K1(-6.175,0.325) K2(-5.525,0.325) K4(-4.225,0.325) K7(-2.275,0.325) K8(-1.625,0.325) K9(-0.975,0.325) K10(-0.325,0.325) K11(0.325,0.325) K12(0.975,0.325) K13(1.625,0.325) K14(2.275,0.325) K17(4.225,0.325) K19(5.525,0.325) K20(6.175,0.325) L1(-6.175,-0.325) L2(-5.525,-0.325) L4(-4.225,-0.325) L7(-2.275,-0.325) L8(-1.625,-0.325) L9(-0.975,-0.325) L10(-0.325,-0.325) L11(0.325,-0.325) L12(0.975,-0.325) L13(1.625,-0.325) L14(2.275,-0.325) L17(4.225,-0.325) L19(5.525,-0.325) L20(6.175,-0.325) M1(-6.175,-0.975) M2(-5.525,-0.975) M3(-4.875,-0.975) M5(-3.575,-0.975) M6(-2.925,-0.975) M7(-2.275,-0.975) M8(-1.625,-0.975) M9(-0.975,-0.975) M10(-0.325,-0.975) M11(0.325,-0.975) M12(0.975,-0.975) M13(1.625,-0.975) M14(2.275,-0.975) M15(2.925,-0.975) M16(3.575,-0.975) M18(4.875,-0.975) M19(5.525,-0.975) M20(6.175,-0.975) N1(-6.175,-1.625) N2(-5.525,-1.625) N4(-4.225,-1.625) N7(-2.275,-1.625) N8(-1.625,-1.625) N9(-0.975,-1.625) N10(-0.325,-1.625) N11(0.325,-1.625) N12(0.975,-1.625) N13(1.625,-1.625) N14(2.275,-1.625) N17(4.225,-1.625) N19(5.525,-1.625) N20(6.175,-1.625) P1(-6.175,-2.275) P2(-5.525,-2.275) P3(-4.875,-2.275) P5(-3.575,-2.275) P6(-2.925,-2.275) P7(-2.275,-2.275) P8(-1.625,-2.275) P9(-0.975,-2.275) P10(-0.325,-2.275) P11(0.325,-2.275) P12(0.975,-2.275) P13(1.625,-2.275) P14(2.275,-2.275) P15(2.925,-2.275) P16(3.575,-2.275) P18(4.875,-2.275) P19(5.525,-2.275) P20(6.175,-2.275) R1(-6.175,-2.925) R2(-5.525,-2.925) R4(-4.225,-2.925) R6(-2.925,-2.925) R7(-2.275,-2.925) R9(-0.975,-2.925) R12(0.975,-2.925) R14(2.275,-2.925) R15(2.925,-2.925) R17(4.225,-2.925) R19(5.525,-2.925) R20(6.175,-2.925) T1(-6.175,-3.575) T2(-5.525,-3.575) T3(-4.875,-3.575) T5(-3.575,-3.575) T7(-2.275,-3.575) T9(-0.975,-3.575) T12(0.975,-3.575) T14(2.275,-3.575) T16(3.575,-3.575) T18(4.875,-3.575) T19(5.525,-3.575) T20(6.175,-3.575) U1(-6.175,-4.225) U2(-5.525,-4.225) U4(-4.225,-4.225) U6(-2.925,-4.225) U8(-1.625,-4.225) U10(-0.325,-4.225) U11(0.325,-4.225) U13(1.625,-4.225) U15(2.925,-4.225) U17(4.225,-4.225) U19(5.525,-4.225) U20(6.175,-4.225) V1(-6.175,-4.875) V2(-5.525,-4.875) V3(-4.875,-4.875) V5(-3.575,-4.875) V7(-2.275,-4.875) V9(-0.975,-4.875) V12(0.975,-4.875) V14(2.275,-4.875) V16(3.575,-4.875) V18(4.875,-4.875) V19(5.525,-4.875) V20(6.175,-4.875) W1(-6.175,-5.525) W2(-5.525,-5.525) W3(-4.875,-5.525) W4(-4.225,-5.525) W5(-3.575,-5.525) W6(-2.925,-5.525) W7(-2.275,-5.525) W8(-1.625,-5.525) W9(-0.975,-5.525) W10(-0.325,-5.525) W11(0.325,-5.525) W12(0.975,-5.525) W13(1.625,-5.525) W14(2.275,-5.525) W15(2.925,-5.525) W16(3.575,-5.525) W17(4.225,-5.525) W18(4.875,-5.525) W19(5.525,-5.525) W20(6.175,-5.525) Y1(-6.175,-6.175) Y2(-5.525,-6.175) Y3(-4.875,-6.175) Y4(-4.225,-6.175) Y5(-3.575,-6.175) Y6(-2.925,-6.175) Y7(-2.275,-6.175) Y8(-1.625,-6.175) Y9(-0.975,-6.175) Y10(-0.325,-6.175) Y11(0.325,-6.175) Y12(0.975,-6.175) Y13(1.625,-6.175) Y14(2.275,-6.175) Y15(2.925,-6.175) Y16(3.575,-6.175) Y17(4.225,-6.175) Y18(4.875,-6.175) Y19(5.525,-6.175) Y20(6.175,-6.175)
  silkscreen extent -6.96,6.71 -6.71,6.96, body extent -6.63,-6.63 6.63,6.63, height 1.5
SMB-Bi [mil] "Molded Diode, 2-Leads, Body 5.4x3.6mm, IPC Medium Density, based on OnSemi component dimensions"
  rect 85x107.99 smd: 1(-87.01,0) 2(87.01,0)
  silkscreen extent -125,-79 125,79, body extent -104,-73 104,73, height 89
SOIC-8 [mm] "duplicate of SO-8.  SOIC, 8-Leads, Body 5.0x4.0mm (max), Pitch 1.27mm, IPC Medium Density"
  rrect17% 1.45x0.6 smd: 1(-2.725,1.905) 2(-2.725,0.635) 3(-2.725,-0.635) 4(-2.725,-1.905) 5(2.725,-1.905) 6(2.725,-0.635) 7(2.725,0.635) 8(2.725,1.905)
  silkscreen extent -3.5,-2.5 0.9,2.5, body extent -3,-2.45 3,2.45, height 1.63
SOT-23 [mm] "SOT23, 3-Leads, Body 2.9x1.3mm, Pitch 0.95mm, Lead Span 2.5mm, IPC Medium Density"
  rrect50% 1x0.6 smd: 1(-1.2,0.95) 2(-1.2,-0.95) 3(1.2,0)
  silkscreen extent -1.63,-1.5 0.7,1.5, body extent -1.16,-1.45 1.21,1.45, height 1
SOT-323 [mm] "Diodes Inc recommended land pattern.  2016-02-24"
  rrect21% 0.6x0.47 smd: 1(-0.95,0.65) 2(-0.95,-0.65) 3(0.95,0)
  silkscreen extent -1.14,-1.22 0.77,1.22, body extent -1.13,-1.13 1.12,1.12, height 1.13
Sullins_PBC02SAAN [mm] "Sullins 100mil, 1x2, 230 mil above insulator"
  rect 1.65x1.65 hole 1.016: 1(0,1.27)
  round 1.65 hole 1.016: 2(0,-1.27)
  silkscreen extent -1.27,-2.54 1.94,2.54, body extent -1.27,-2.54 1.27,2.54, height 8.38
Sullins_PxC05SAAN [mm] "Header, 2.54mm, 5x1, TH"
  rect 1.55x1.55 hole 1.016: 1(-5.08,0)
  round 1.55 hole 1.016: 2(-2.54,0) 3(0,0) 4(2.54,0) 5(5.08,0)
  silkscreen extent -6.35,-1.75 6.35,1.27, body extent -6.35,-1.27 6.35,1.27, height 5.84
Sullins_xxPC005DAAN-RC [mm] "Header, 2.54mm, 5x2, TH"
  rrect50% 1.5x1.5 hole 1: 1(-1.27,5.08)
  round 1.5 hole 1: 2(1.27,5.08) 3(-1.27,2.54) 4(1.27,2.54) 5(-1.27,0) 6(1.27,0) 7(-1.27,-2.54) 8(1.27,-2.54) 9(-1.27,-5.08) 10(1.27,-5.08)
  body extent -2.5,-6.35 2.5,6.35, height 8.34
SW_CAS-120TA [mm] "COPAL ELECTRONICS"
  rect 1.6x1 smd: 1(-1.15,1.75) 2(1.15,0) 3(-1.15,-1.75)
  silkscreen extent -2,-2.85 1.4,2.93, body extent -1.4,-2.85 1.4,2.85, height 2.51
SW_CAS-D20TA [mm] "SMD, 6-Leads, Body 5.4x3.9mm, Pitch 1.75mm"
  rect 1.6x1 smd: 1(-1.85,1.75) 2(-1.85,0) 3(-1.85,-1.75) 4(1.85,1.75) 5(1.85,0) 6(1.85,-1.75)
  silkscreen extent -1.95,-2.7 1.95,2.9, body extent -2.1,-2.7 2.1,2.7, height 2.5
TFM252012 [mm] "SMD, 2-Leads, Body 2.5x2mm"
  rect 0.7x2 smd: 1(-1.1,0) 2(1.1,0)
  silkscreen extent -0.45,-1.1 0.45,1.1, body extent -1.35,-1.1 1.35,1.1, height 1.2
TI_Stacked_Overlay_Small [mil]
  silkscreen extent -418,-98 418,98
TP_25MIL-SMT [mil]
  round 25 smd mask-2.5: 1(0,0)
TP_SM_1MM [mm] "1mm Test Point, SMT"
  round 1 smd paste-0.5: 1(0,0)
WEEE_Minimum [mil] "WEEElie bin"
  silkscreen extent -95,-172 99,104
WL-SMCW_GREEN [mm] "WURTH"
  rect 0.8x0.8 smd: 1(-0.8,0) 2(0.8,0)
  silkscreen extent -1.9,-0.8 1.2,0.8, body extent -0.85,-0.45 0.85,0.45, height 0.8
WL-SMCW_RED [mm] "WURTH"
  rect 0.8x0.8 smd: 1(-0.8,0) 2(0.8,0)
  silkscreen extent -1.9,-0.8 1.2,0.8, body extent -0.85,-0.45 0.85,0.45, height 0.8
Wurth_60900213421 [mil] "Shunt, 2.54mm, Black"
  round 1 on Mech3: 0(0,0)
  body extent -98,-48 98,48, height 338

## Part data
C1 C57 C264 C271: library part CMP-0009436-2, "CAP, CERM, 1000 pF, 2000 V, +/- 10%, X7R, 1808", Cap_Case=1808, Manufacturer=MuRata, Supplier Part Number 1=490-8145-1-ND, TempCo=X7R, Tolerance_%=10%, Value1=Unknown, Value2=2000V, ValueDisplayed=1000pF
C2 C23: library part CMP-0006526-2, "CAP, CERM, 2.2 uF, 16 V, +/- 10%, X6S, 0402", Cap_Case=0402, Manufacturer=MuRata, Supplier Part Number 1=GRM155C81C225KE11D-ND, TempCo=X6S, Tolerance_%=10%, Value1=Unknown, Value2=16V, ValueDisplayed=2.2uF
C3 C6 C7 C8 C9 C10 C11 C16 C17 C19 C20 C24 C26 C28 C29 C30 C32 C33 C34 C36 C37 C42 C43 C49 C52 C53 C54 C59 C72 C86 C103 C107 C108 C109 C112 C116 C119 C121 C124 C127 C128 C129 C134 C136 C137 C138 C142 C146 C157 C160 C163 C198 C231 C233 C237 C238 C256 C257 C258 C259 C260 C265 C266 C268: library part CMP-0006659-2, "CAP, CERM, 0.1 uF, 25 V, +/- 10%, X7R, 0402", Cap_Case=0402, Manufacturer=MuRata, Supplier Part Number 1=490-10698-1-ND, TempCo=X7R, Tolerance_%=10%, Value1=Unknown, Value2=25V, ValueDisplayed=0.1uF
C4 C12 C31 C41: library part CMP-0079201-1, "CAP, CERM, 10 µF, 50 V,+/- 10%, X7R, 1210", Cap_Case=1210, Manufacturer="Samsung Electro-Mechanics", Supplier Part Number 1=1276-3388-1-ND, TempCo=X7R, Tolerance_%=10%, Value1="0.005 ohm", Value2=50V, ValueDisplayed=10µF
C5 C51: library part CMP-0007470-5, "CAP, CERM, 0.1 uF, 100 V, +/- 10%, X7R, 0603", Cap_Case=0603, Manufacturer=MuRata, Supplier Part Number 1=490-6439-1-ND, TempCo=X7R, Tolerance_%=10%, Value1=Unknown, Value2=100V, ValueDisplayed=0.1uF
C13: library part CMP-0006420-2, "CAP, CERM, 15 pF, 50 V, +/- 5%, C0G/NP0, 0402", Cap_Case=0402, Manufacturer=MuRata, Supplier Part Number 1=81-GRM1555C1H150JA1D, TempCo=C0G/NP0, Tolerance_%=5%, Value1=Unknown, Value2=50V, ValueDisplayed=15pF
C14 C18 C21 C25 C56 C76 C250: library part CMP-0035346-1, "1µF ±10% 10V Ceramic Capacitor X7S 0402 (1005 Metric)", Digikey Part Number=490-14457-1-ND, Manufacturer=Murata, Mouser Part Number=81-GRM155C71A105KE1D, Operating Temperature Range="-55°C to +125°C", TempCo=22%, Temperature Characteristic=X7S, Tolerance_%=10%, ValueDisplayed=1uF
C15 C22 C27 C35 C39: library part CMP-0085850-1, "CAP, CERM, 0.1 µF, 16 V,+/- 10%, X7R, 0402", Cap_Case=0402, Manufacturer=Walsin, TempCo=X7R, Tolerance_%=10%, Value2=16V, ValueDisplayed=0.1µF
C38: library part CMP-0006638-1, "CAP, CERM, 1000 pF, 16 V, +/- 10%, X7R, 0402", Cap_Case=0402, Manufacturer=MuRata, Supplier Part Number 1=GRM155R71C102KA01D-ND, TempCo=X7R, Tolerance_%=10%, Value1=Unknown, Value2=16V, ValueDisplayed=1000pF
C40 C261 C267 C269: library part CMP-0006658-2, "CAP, CERM, 0.01 uF, 25 V, +/- 10%, X7R, 0402", Cap_Case=0402, Manufacturer=MuRata, Supplier Part Number 1=490-1312-1-ND, TempCo=X7R, Tolerance_%=10%, Value1=Unknown, Value2=25V, ValueDisplayed=0.01uF
C44 C118 C248: library part CMP-0043010-1, "10 µF ±20% 10V Ceramic Capacitor X5R 0402 (1005 Metric)", Digikey Part Number=478-KGM05CR51A106MHCT-ND, Manufacturer="KYOCERA AVX", Mouser Part Number=581-KGM05CR51A106MH, Operating Temperature Range="-55°C to +85°C", TempCo=15%, Temperature Characteristic=X5R, Tolerance_%=20%, ValueDisplayed=10uF
C45 C46: library part CMP-0096855-1, "Chip Multilayer Ceramic Capacitors for General Purpose, 0402, 0.10uF, X7R, 15%, 10%, 50V", Manufacturer=Murata, Operating Temperature Range="-55°C to +125°C", TempCo=15%, Temperature Characteristic=X7R, Tolerance_%=10%, ValueDisplayed=0.10uF
C47 C50 C270: library part CMP-0008378-2, "CAP, CERM, 10 uF, 25 V, +/- 10%, X7R, 0805", Cap_Case=0805, Manufacturer=MuRata, Supplier Part Number 1=81-GRM21BZ71E106KE5L, TempCo=X7R, Tolerance_%=10%, Value1=Unknown, Value2=25V, ValueDisplayed=10uF
C48: library part CMP-0006610-2, "CAP, CERM, 2.2 uF, 25 V, +/- 10%, X5R, 0402", Cap_Case=0402, Manufacturer=MuRata, Supplier Part Number 1=GRM155R61E225KE11D-ND, TempCo=X5R, Tolerance_%=10%, Value1=Unknown, Value2=25V, ValueDisplayed=2.2uF
C55 C158 C161 C162 C165 C180 C188 C189 C206 C228 C232 C234 C235 C240 C241: library part CMP-0042976-1, "Cap Ceramic 3.3uF 10V X5R ±10% Pad SMD 0603 +85°C T/R", Digikey Part Number=1276-1892-1-ND, Manufacturer=Samsung, Mouser Part Number=187-CL10A335KP8NNNC, Operating Temperature Range="-55°C to +85°C", TempCo=15%, Temperature Characteristic=X5R, Tolerance_%=10%, ValueDisplayed=3.3uF
C58 C70 C144 C145 C147 C239: library part CMP-0007144-4, "CAP, CERM, 0.1 uF, 50 V, +/- 10%, X7R, 0603", Cap_Case=0603, Manufacturer=MuRata, Supplier Part Number 1=490-4779-1-ND, TempCo=X7R, Tolerance_%=10%, Value1="0.02 ohm", Value2=50V, ValueDisplayed=0.1uF
C60 C254: library part CMP-0076706-1, "CAP, CERM, 4.7 µF, 25 V,+/- 10%, X7R, AEC-Q200 Grade 1, 0805", Cap_Case=2x1.25x1.25mm, Manufacturer=TDK, Supplier Part Number 1=445-6967-1-ND, TempCo=X7R, Tolerance_%=10%, Value2=25V, ValueDisplayed=4.7µF
C61 C69 C71 C75 C77 C83 C244 C245 C252: library part CMP-0006349-2, "CAP, CERM, 1 uF, 10 V, +/- 10%, X7S, AEC-Q200 Grade 1, 0402", Cap_Case=0402, Manufacturer=MuRata, Supplier Part Number 1=81-GCM155C71A105KE8D, TempCo=X7S, Tolerance_%=10%, Value1=Unknown, Value2=10V, ValueDisplayed=1uF
C62 C63 C66 C68 C73 C79 C80 C81 C82 C87 C249 C255: library part CMP-0006326-2, "CAP, CERM, 0.1 uF, 50 V, +/- 20%, X7R, AEC-Q200 Grade 1, 0402", Cap_Case=0402, Manufacturer=TDK, Supplier Part Number 1=445-12271-1-ND, TempCo=X7R, Tolerance_%=20%, Value1=Unknown, Value2=50V, ValueDisplayed=0.1uF
C64 C67 C85 C131 C132 C133 C135 C139 C140 C242 C251: library part CMP-0089543-1, "10µF ±10% 10V Ceramic Capacitor X7S 0805 (2012 Metric)", Digikey Part Number=445-173805-1-ND, Manufacturer=TDK, Mouser Part Number=810-CG4J3X7S1A106KAE, Operating Temperature Range="-55°C to +125°C", TempCo=22%, Temperature Characteristic=X7S, Tolerance_%=10%, ValueDisplayed=10uF
C65 C78 C159 C166 C169 C171 C172 C173 C174 C175 C176 C177 C179 C186 C190 C191 C192 C193 C197 C199 C200 C201 C203 C204 C205 C207 C209 C210 C211 C213 C214 C215 C216 C218 C219 C220 C221 C222 C223 C224 C225 C226 C227 C230 C236: library part CMP-0064970-1, "CAP, CERM, 0.1 uF, 16 V,+/- 10%, X7R, 0201", Cap_Case=0201, Manufacturer=MuRata, Supplier Part Number 1=81-GRM033Z71C104KE4D, TempCo=X7R, Tolerance_%=10%, Value1=Unknown, Value2=16V, ValueDisplayed=0.1uF
C74 C115 C117 C120 C122 C123 C125 C126 C143 C154 C156 C246 C247 C253: library part CMP-0006221-2, "CAP, CERM, 0.1 uF, 10 V, +/- 20%, X5R, 0402", Cap_Case=0402, Manufacturer="Wurth Elektronik", Supplier Part Number 1=732-7487-1-ND, TempCo=X5R, Tolerance_%=20%, Value1=Unknown, Value2=10V, ValueDisplayed=0.1uF
C84 C243: library part CMP-0094207-1, "Cap Ceramic 2.2uF 10V X7S 10% Pad SMD 0603 +125°C Automotive T/R", Manufacturer=TDK, Operating Temperature Range="-55°C to +125°C", TempCo=0.22, Temperature Characteristic=X7S, Tolerance_%=0.1%, ValueDisplayed=2.2uF
C88 C89: library part CMP-0035228-1, "Multi-Layer Ceramic Capacitor 12pF C0G  ±5% 0402 Paper T/R", Manufacturer=Murata, Operating Temperature Range="-55°C to +125°C", TempCo=30ppm/°C, Temperature Characteristic=C0G, Tolerance_%=5%, ValueDisplayed=12pF
C90 C91 C92 C93 C94 C95 C96 C97 C98 C99 C100 C101 C102 C104 C105 C106 C164 C167 C170 C178 C195: library part CMP-0006456-2, "CAP, CERM, 330 pF, 50 V, +/- 5%, C0G/NP0, 0402", Cap_Case=0402, Manufacturer=MuRata, Supplier Part Number 1=490-1295-1-ND, TempCo=C0G/NP0, Tolerance_%=5%, Value1=Unknown, Value2=50V, ValueDisplayed=330pF
C110 C148 C149 C152 C153 C155: library part CMP-0007173-4, "CAP, CERM, 1000 pF, 50 V, +/- 5%, C0G/NP0, 0603", Cap_Case=0603, Manufacturer=MuRata, Supplier Part Number 1=490-1451-1-ND, TempCo=C0G/NP0, Tolerance_%=5%, Value1=Unknown, Value2=50V, ValueDisplayed=1000pF
C111 C113 C168 C202: library part CMP-0007498-4, "CAP, CERM, 4.7 uF, 10 V, +/- 20%, X7R, 0603", Cap_Case=0603, Manufacturer=MuRata, TempCo=X7R, Tolerance_%=20%, Value1=Unknown, Value2=10V, ValueDisplayed=4.7uF
C114: library part CMP-0006692-2, "CAP, CERM, 4700 pF, 50 V, +/- 10%, X7R, 0402", Cap_Case=0402, Manufacturer=MuRata, Supplier Part Number 1=490-1308-1-ND, TempCo=X7R, Tolerance_%=10%, Value1=Unknown, Value2=50V, ValueDisplayed=4700pF
C130 C141: library part CMP-0006623-2, "CAP, CERM, 0.1 uF, 6.3 V, +/- 10%, X7R, 0402", Cap_Case=0402, Manufacturer=MuRata, Supplier Part Number 1=GRM155R70J104KA01D-ND, TempCo=X7R, Tolerance_%=10%, Value1=Unknown, Value2=6.3V, ValueDisplayed=0.1uF
C150 C151: library part CMP-0006841-4, "CAP, CERM, 100 pF, 50 V, +/- 5%, C0G/NP0, 0603", Cap_Case=0603, Manufacturer=Kemet, Supplier Part Number 1=399-1061-1-ND, TempCo=C0G/NP0, Tolerance_%=5%, Value1=Unknown, Value2=50V, ValueDisplayed=100pF
C181 C182 C183 C184 C185 C187 C194 C196 C208 C212 C217 C229: library part CMP-0093721-1, "Chip Multilayer Ceramic Capacitors for General Purpose, 0201, 1.0uF, X6S, 22%, 20%, 6.3V", Manufacturer=Murata, Operating Temperature Range="-55°C to +105°C", TempCo=22%, Temperature Characteristic=X6S, Tolerance_%=20%, ValueDisplayed=1.0uF
C262 C263: library part CMP-0087060-3, "Cap Ceramic 8pF 50V C0G 0.5pF SMD 0402 125C Paper T/R", Manufacturer="Murata Electronics North America", TempCo=30ppm/°C
D1 D3 D4 D5 D6 D7 D8 D9 D10 D11 D12 D13 D14 D15 D16: library part CMP-0002894-2, "LED, Green, SMD", Color=green, Manufacturer="Wurth Elektronik", Value1=W, Value2=2V
D2 D18 D19: library part CMP-0005599-2, "Diode, TVS, Bi, 6.5 V, SMB", Manufacturer=Littelfuse, Value1=600W
D17: library part CMP-0073602-3, "1-Channel ESD Protection Diode for USB Type-C and Thunderbolt 3, DPY0002A (X1SON-2)", Alternate Manufacturer="Texas Instruments", Alternate PartNumber=TPD1E01B04DPYT, Operating Temperature Range="-40 to 125 C", Rating=Catalog
DS1 DS2 DS3: library part CMP-0002947-3, "LED, Red, SMD", Color=Red, Manufacturer="Wurth Elektronik", Power_TotalModule=72mW, Value1=0.072W, Value2=2V
FB1 FB2 FB3 FB4: library part CMP-0089199-1, "120 Ohms @ 100MHz 1  Ferrite Bead 0603 (1608 Metric) 2A 40mOhm", Digikey Part Number=490-3991-1-ND, Impedance At Frequency="120Ω @ 100MHz", Manufacturer=Murata, Mouser Part Number=81-BLM18EG121SN1D, Operating Temperature Range="-55°C to +125°C", Tolerance_%=25%
FID1 FID1_1 FID1_1_1 FID1_1_2 FID1_1_3 FID2 FID3 FID4 FID4_1 FID4_1_1 FID4_1_2 FID4_1_3 FID5 FID6: library part CMP-0077181-1, "Fiducial mark.  There is nothing to buy or mount.", Manufacturer=N/A
J1/J3: library part CMP-0003837-4, "Receptacle, 2.54mm, 10x2, Tin, TH", Alternate Manufacturer="Major League Electronics", Alternate PartNumber=CRD-081413-A-G, Manufacturer=Samtec, Supplier Part Number 1=SAM1204-10-ND
J2/J4: library part CMP-0078266-4, "Receptacle, 2.54mm, 10x2, Tin, TH", Alternate Manufacturer="Major League Electronics", Alternate PartNumber=CRD-081413-A-G, Manufacturer=Samtec, Supplier Part Number 1=SAM1204-10-ND
J5/J7: library part CMP-0081070-3, "Receptacle, 2.54mm, 10x2, Tin, TH", Alternate Manufacturer="Major League Electronics", Alternate PartNumber=CRD-081413-A-G, Manufacturer=Samtec, Supplier Part Number 1=SAM1204-10-ND
J6/J8: library part CMP-0081071-3, "Receptacle, 2.54mm, 10x2, Tin, TH", Alternate Manufacturer="Major League Electronics", Alternate PartNumber=CRD-081413-A-G, Manufacturer=Samtec, Supplier Part Number 1=SAM1204-10-ND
